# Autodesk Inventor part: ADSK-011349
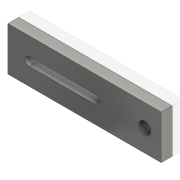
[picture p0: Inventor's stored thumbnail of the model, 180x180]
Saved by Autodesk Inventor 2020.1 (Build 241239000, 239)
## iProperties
Created: 1999-12
Part Number: ADSK-011349
Material: Pearson HRS
Document SubType Name: Modeling
Designer: glanglot
Density: 7.83 g/cm^3
Appearance: Steel
Mass: 791.724 g
Surface Area: 247.393 cm^2
Volume: 101.114 cm^3
Control State: 0
Master: False
Checked Out: False
Shininess: 25.0
Length Units: 11269
Angle Units: 11279
Time Units: 11290
Mass Units: 11283
Length Display Precision: 3
Angle Display Precision: 2
Compacted: True
Cutlength: 7.00
Material Desc: FLAT,HRS,0.500X02.00
Material_Number: A084313
Dimensions: 178x51x12,5 mm
Mass: 0,792 kg
Density: 7.829999999999999
Volumn: 101.60716921344843
Area: 247.2734133349311
PropertySet Name: Model Information
Author: glanglot
Revision Number: -
Title: ADSK-011349
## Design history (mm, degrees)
node "Solide1"
  node "Extrusion1" dims "d2" = 12.5, "d3" = 0
  node "Extrusion3" dims "d19" = 12.7, "d20" = 0
  node "Hole2" dims "d24" = 13.835, "d25" = 9.525, "d26" = 6.35, "d27" = 60 deg, "d28" = 41.3, "d29" = 118 deg, "d30" = 32
sketch "Sketch1"
  geometry: L1 (-89, 25.5)-(89, 25.5); L2 (89, 25.5)-(89, -25.5); L3 (89, -25.5)-(-89, -25.5); L4 (-89, -25.5)-(-89, 25.5); 3 further points
  constraints: 8 end point, 2 midpoint, 2 parallel, 1 horizontal, 1 horizontal alignment, 1 perpendicular, 1 vertical alignment
  dimensions: "d0" = 51 distance of L3.end L1.start; "d1" = 178 distance of L2.end L3.end
sketch "Sketch5"
  geometry: L1 (-89, -25.5)-(-89, 25.5) reference; L2 (-64, 5)-(12, 5); L3 (12, 5)-(12, -5); L4 (12, -5)-(-64, -5); L5 (-64, -5)-(-64, 5); A1 r 5 centre (-64, 0) between (-64, 5) and (-64, -5); A2 r 5 centre (12, 0) between (12, -5) and (12, 5); 2 further points
  constraints: 8 end point, 4 point on circle, 4 tangent, 2 centre point, 2 midpoint, 2 parallel, 1 horizontal alignment, 1 perpendicular
  dimensions: "d15" = 5 radius of A1; "d16" = 76 distance between parallel lines of L3 L5; "d18" = 25 distance between parallel lines of L5 L1
sketch "Sketch6"
  geometry: L1 (89, 25.5)-(89, -25.5) reference; L2 (-89, -25.5)-(-89, 25.5) reference; L3 (89, 0)-(-89, 0); 1 further point
  constraints: 2 end point, 2 midpoint, 1 point on line
  dimensions: "d23" = 19 distance from line of L2 point (-70, 0)
node "Corps solides"
node "Corps surfaciques"
